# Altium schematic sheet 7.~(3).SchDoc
size 420 x 297 mm
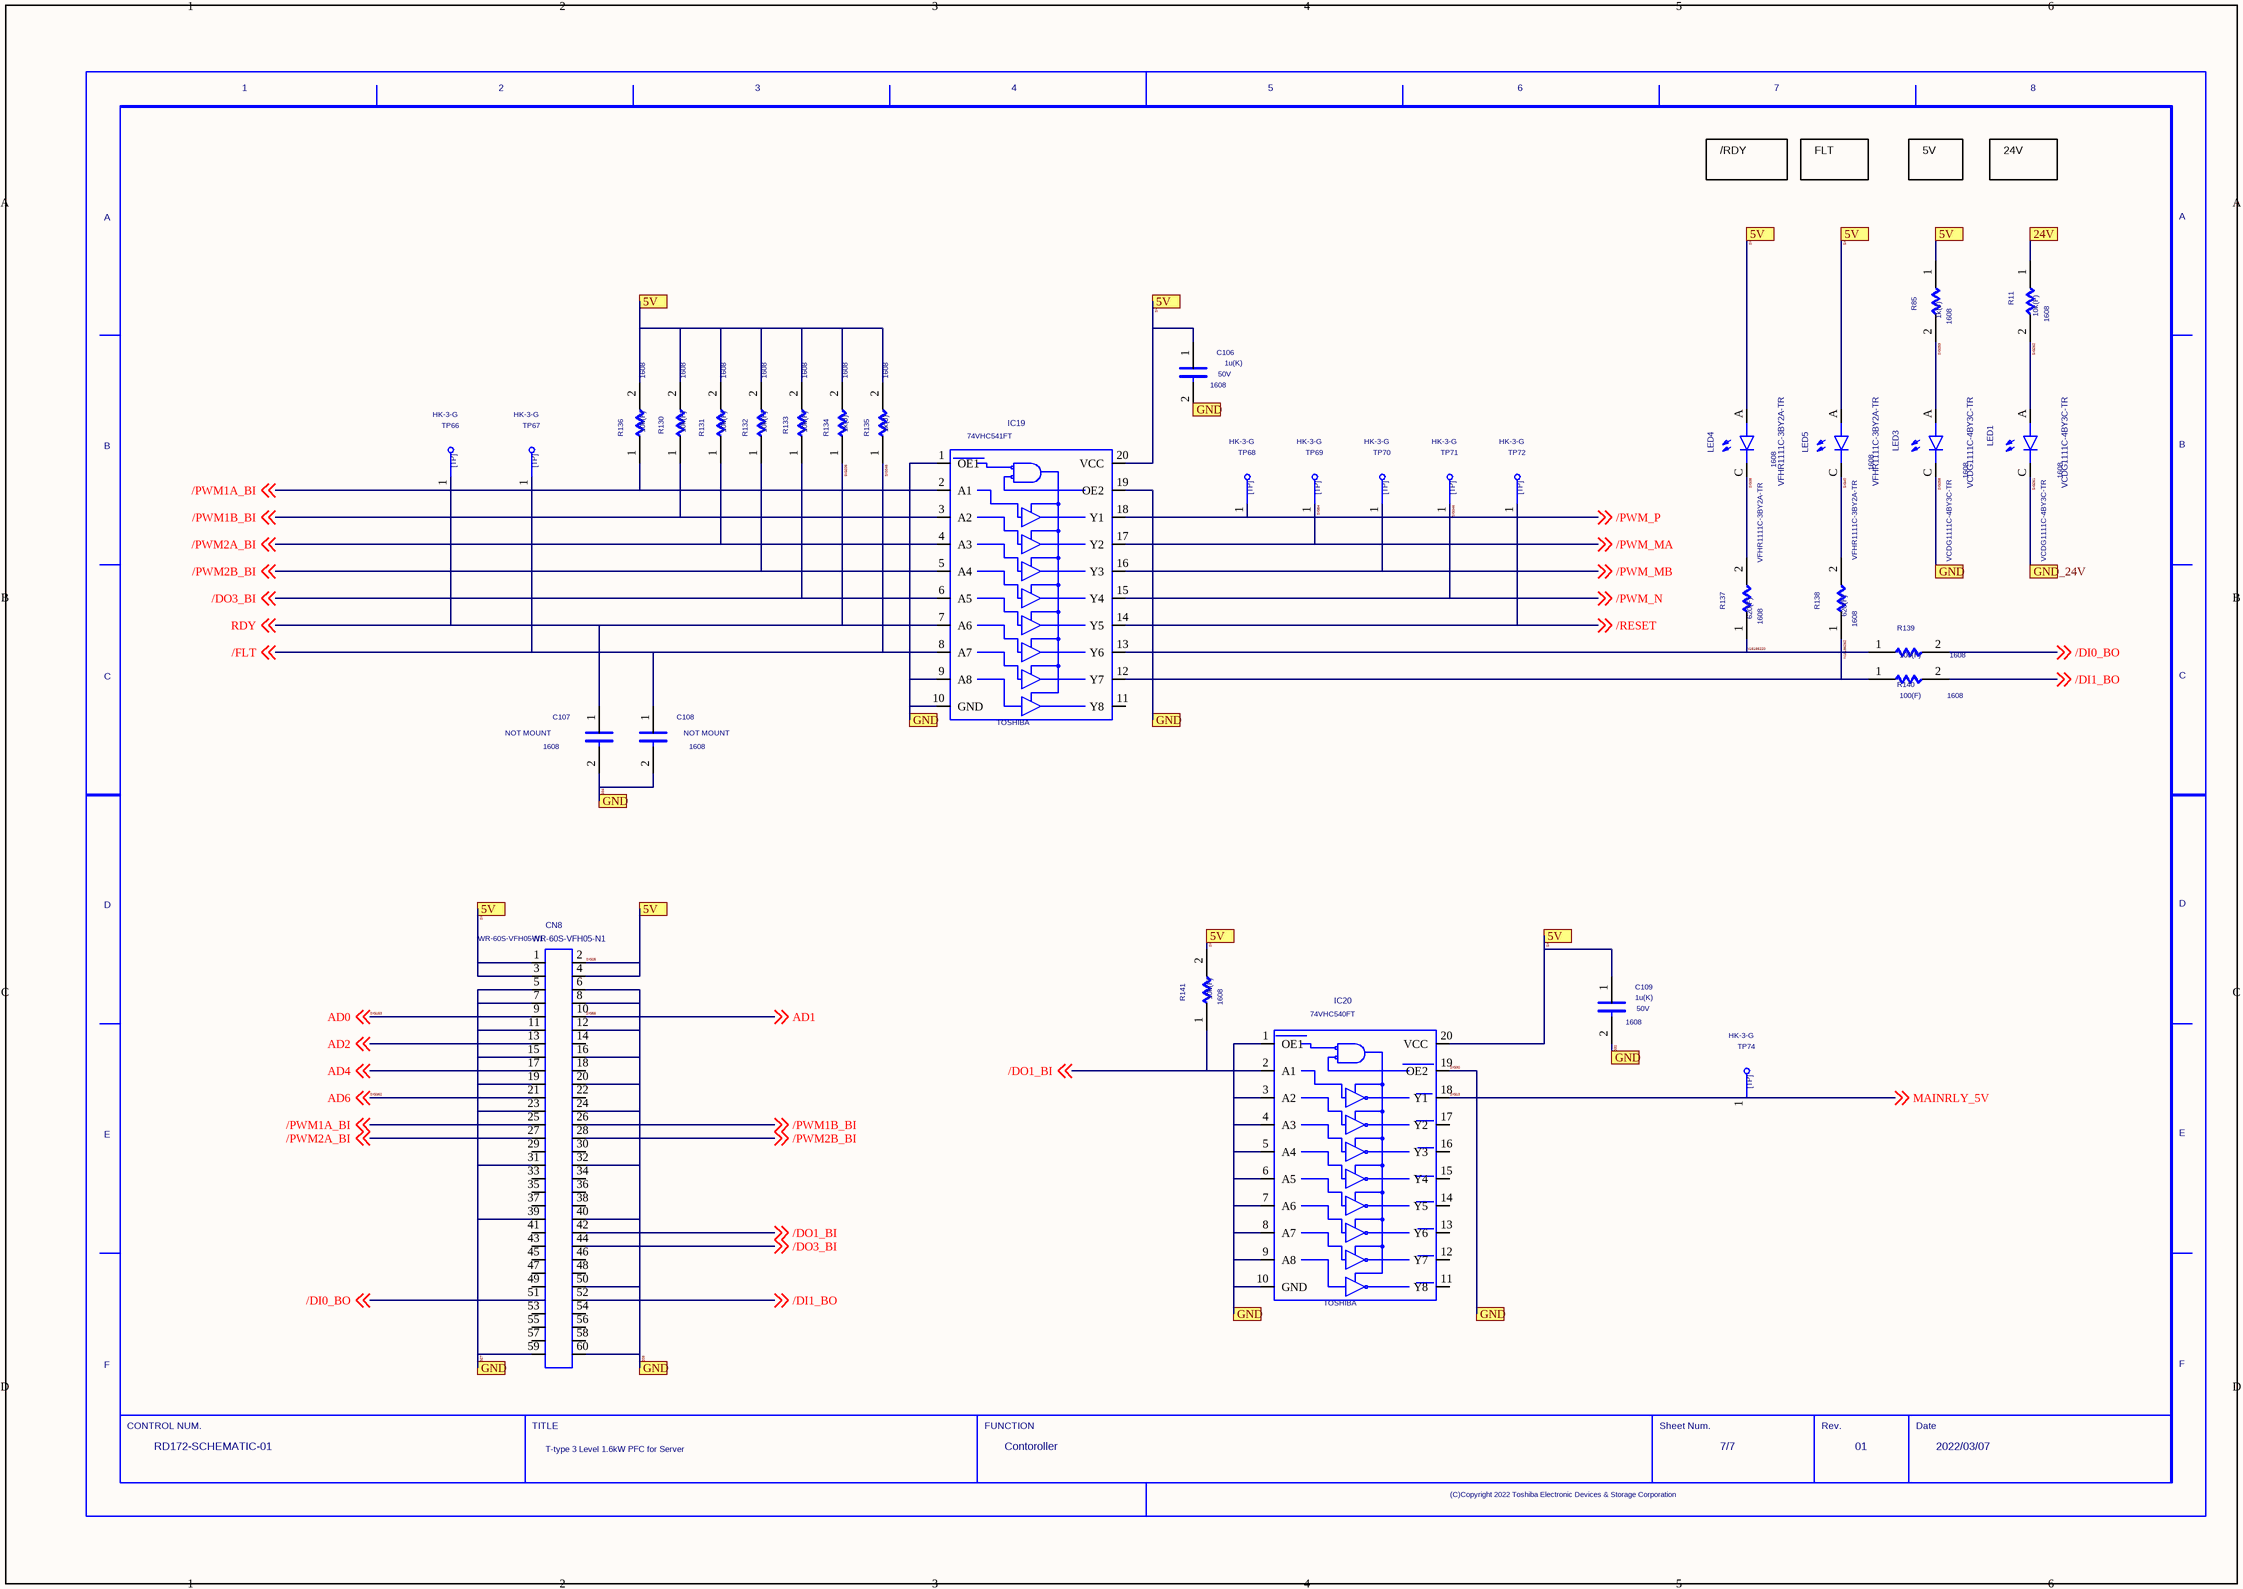
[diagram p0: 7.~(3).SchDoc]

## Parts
C106  SIZECODESMD: 1608  VAL2: 50V  VAL1: 1u(K)  (hidden comment: C)
C107  SIZECODESMD: 1608  NOTMOUNT: NOT MOUNT  (hidden comment: C)
C108  SIZECODESMD: 1608  NOTMOUNT: NOT MOUNT  (hidden comment: C)
C109  SIZECODESMD: 1608  VAL2: 50V  VAL1: 1u(K)  (hidden comment: C)
CN8  WR-60S-VFH05-N1
IC19  USERCOMPTEXT3: TOSHIBA  (hidden comment: 74VHC541FT)
IC20  USERCOMPTEXT3: TOSHIBA  (hidden comment: 74VHC540FT)
LED1  VCDG1111C-4BY3C-TR  SIZECODESMD: 1608
LED3  VCDG1111C-4BY3C-TR  SIZECODESMD: 1608
LED4  VFHR1111C-3BY2A-TR  SIZECODESMD: 1608
LED5  VFHR1111C-3BY2A-TR  SIZECODESMD: 1608
R11  SIZECODESMD: 1608  VAL1: 10k(F)  (hidden comment: R)
R85  SIZECODESMD: 1608  VAL1: 1k(J)  (hidden comment: R)
R130  SIZECODESMD: 1608  VAL1: 10k(F)  (hidden comment: R)
R131  SIZECODESMD: 1608  VAL1: 10k(F)  (hidden comment: R)
R132  SIZECODESMD: 1608  VAL1: 10k(F)  (hidden comment: R)
R133  SIZECODESMD: 1608  VAL1: 10k(F)  (hidden comment: R)
R134  SIZECODESMD: 1608  VAL1: 1k(J)  (hidden comment: R)
R135  SIZECODESMD: 1608  VAL1: 1k(J)  (hidden comment: R)
R136  SIZECODESMD: 1608  VAL1: 10k(F)  (hidden comment: R)
R137  SIZECODESMD: 1608  VAL1: 620(F)  (hidden comment: R)
R138  SIZECODESMD: 1608  VAL1: 620(F)  (hidden comment: R)
R139  SIZECODESMD: 1608  VAL1: 100(F)  (hidden comment: R)
R140  SIZECODESMD: 1608  VAL1: 100(F)  (hidden comment: R)
R141  SIZECODESMD: 1608  VAL1: 10k(F)  (hidden comment: R)
TP66  VAL3: HK-3-G  (hidden comment: TP)
TP67  VAL3: HK-3-G  (hidden comment: TP)
TP68  VAL3: HK-3-G  (hidden comment: TP)
TP69  VAL3: HK-3-G  (hidden comment: TP)
TP70  VAL3: HK-3-G  (hidden comment: TP)
TP71  VAL3: HK-3-G  (hidden comment: TP)
TP72  VAL3: HK-3-G  (hidden comment: TP)
TP74  VAL3: HK-3-G  (hidden comment: TP)
U?  DATE: 2022/03/07  REVISION: 01  SHEETNUMBER: 7/7  FUNCTION: Contoroller  TITLE: T-type 3 Level 1.6kW PFC for Server  DRAWINGNUMBER: RD172-SCHEMATIC-01  (hidden comment: WAKU_DEF100)

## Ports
5V, 24V, GND, GND_24V

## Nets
24V: R11.1 ; port 24V
/DI0_BO: CN8.51 R139.2 ; off-sheet /DI0_BO
/DI1_BO: CN8.52 R140.2 ; off-sheet /DI1_BO
/DO1_BI: CN8.42 IC20.2(A1) R141.1 ; off-sheet /DO1_BI
/DO3_BI: CN8.44 IC19.6(A5) R133.1 ; off-sheet /DO3_BI
/PWM1A_BI: CN8.25 IC19.2(A1) R136.1 ; off-sheet /PWM1A_BI
/PWM1B_BI: CN8.26 IC19.3(A2) R130.1 ; off-sheet /PWM1B_BI
/PWM2A_BI: CN8.27 IC19.4(A3) R131.1 ; off-sheet /PWM2A_BI
/PWM2B_BI: CN8.28 IC19.5(A4) R132.1 ; off-sheet /PWM2B_BI
/PWM_MB: IC19.16(Y3) TP70.1 ; off-sheet /PWM_MB
/PWM_P: IC19.18(Y1) TP68.1 ; off-sheet /PWM_P
/RESET: IC19.14(Y5) TP72.1 ; off-sheet /RESET
AD2: CN8.13 ; off-sheet AD2
AD4: CN8.17 ; off-sheet AD4
N18186220: IC19.13(Y6) R137.1 R139.1
N18186262: IC19.12(Y7) R138.1 R140.1
SIG13: IC20.18(Y1) TP74.1 ; off-sheet MAINRLY_5V  [also labelled MAINRLY_5V]
SIG24: C106.1 C109.1 CN8.1 CN8.2 CN8.3 CN8.4 IC19.20(VCC) IC20.20(VCC) LED4.A LED5.A R85.1 R130.2 R131.2 R132.2 R133.2 R134.2 R135.2 R136.2 R141.2 ; port 5V  [also labelled SIG25, SIG28, SIG31, SIG36, SIG37, SIG39]
SIG38: LED4.C R137.2
SIG40: LED5.C R138.2
SIG55: CN8.10 ; off-sheet AD1  [also labelled AD1]
SIG84: IC19.17(Y2) TP69.1 ; off-sheet /PWM_MA  [also labelled /PWM_MA]
SIG153: CN8.9 ; off-sheet AD0  [also labelled AD0]
SIG205: C107.1 IC19.7(A6) R134.1 TP66.1 ; off-sheet RDY  [also labelled RDY]
SIG208: C106.2 C107.2 C108.2 C109.2 CN8.5 CN8.6 CN8.7 CN8.8 CN8.11 CN8.12 CN8.15 CN8.16 CN8.19 CN8.20 CN8.23 CN8.24 CN8.31 CN8.32 CN8.39 CN8.40 CN8.50 CN8.59 CN8.60 IC19.1(OE1) IC19.9(A8) IC19.10(GND) IC19.19(OE2) IC20.1(OE1) IC20.3(A2) IC20.4(A3) IC20.5(A4) IC20.6(A5) IC20.7(A6) IC20.8(A7) IC20.9(A8) IC20.10(GND) IC20.19(OE2) LED3.C ; port GND  [also labelled SIG258, SIG27, SIG30, SIG32, SIG34]
SIG259: LED3.A R85.2
SIG261: LED1.C ; port GND_24V
SIG262: LED1.A R11.2
SIG345: C108.1 IC19.8(A7) R135.1 TP67.1 ; off-sheet /FLT  [also labelled /FLT]
SIG346: IC19.15(Y4) TP71.1 ; off-sheet /PWM_N  [also labelled /PWM_N]
SIG362: CN8.21 ; off-sheet AD6  [also labelled AD6]

Not connected (* = marked no-connect by the designer): CN8 14 18 22 29 30 33 34 35 36 37 38 41 43 45 46 47 48 49 53 54 55 56 57 58; IC19 11(Y8); IC20 11(Y8) 12(Y7) 13(Y6) 14(Y5) 15(Y4) 16(Y3) 17(Y2)

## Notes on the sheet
- /RDY
- FLT
- 5V
- 24V

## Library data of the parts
C106 C109 = C: OriginalSymbolOrigin: (2540,7620); COMP: -C-UMK107AB7105KA-T
C107 C108 = C: OriginalSymbolOrigin: (2540,7620); COMP: -C-NC_C1608
CN8 = WR_60S_VFH05_N1: Terminal, 200V, 0.3A; MANUFACTURER: JAE; COMP: -CN-WR-60S-VFH05-N1; NOTE: 60pin; TIME: 16:53:54; UPDATEUSER: t5459927; UPDATETIME: 14:46:38; SAVECOUNT: 2; SAVEAREA0: -56595,-80318,58967,4405; OriginalSymbolOrigin: (0,0)
IC19 = 74VHC541FT_0: Buffer; COMP: -IC-74VHC541FT; TIME: 16:53:58; UPDATEUSER: t5459927; UPDATETIME: 14:50:23; SAVECOUNT: 2; SAVEAREA0: -22847,-24597,51708,30063; OriginalSymbolOrigin: (0,0)
IC20 = 74VHC540FT: Buffer; COMP: -IC-74VHC540FT; TIME: 16:53:55; UPDATEUSER: t5459927; UPDATETIME: 14:48:47; SAVECOUNT: 2; SAVEAREA0: -22628,-27657,51926,27001; OriginalSymbolOrigin: (0,0)
LED1 LED3 = VCDG1111C_4BY3C_TR: LED; MANUFACTURER: STANLEY; COMP: -LED-VCDG1111C-4BY3C-TR_AC; NOTE: Green; TIME: 16:53:54; UPDATEUSER: t5459927; SAVECOUNT: 1; OriginalSymbolOrigin: (0,-2540); INSTANCENAME: INS18172566
LED4 LED5 = VFHR1111C_3BY2A_TR: LED; MANUFACTURER: STANLEY; COMP: -LED-VFHR1111C-3BY2A-TR_AC; NOTE: Red; TIME: 16:53:54; UPDATEUSER: t5459927; SAVECOUNT: 1; OriginalSymbolOrigin: (0,-2540); INSTANCENAME: INS18256251
R11 R130-R133 R136 R141 = R: OriginalSymbolOrigin: (5080,5080); VAL2: 100mW; COMP: -R-ERJ3EKF1002V
R85 R134 R135 = R: OriginalSymbolOrigin: (5080,5080); VAL2: 125mW; COMP: -R-RK73B1JTTD102J
R137 R138 = R: OriginalSymbolOrigin: (5080,5080); COMP: -R-ERJ3EKF6200V; VAL2: 100mW
R139 R140 = R: OriginalSymbolOrigin: (5080,5080); COMP: -R-ERJ3EKF1000V; VAL2: 100mW
TP66-TP72 TP74 = TP: TIME: 16:12:21; UPDATEUSER: fukuda-y; UPDATETIME: 16:18:11; SAVECOUNT: 2; SAVEAREA0: -242,-92,12810,7836; OriginalSymbolOrigin: (0,7620); COMP: -TP-HK-3-G
U? = WAKU_DEF100: PLOTTIME: HH:MM; SAVEAREA0: 22200,72372,612276,319236; TIME: 14:30:25; UPDATEUSER: t5459927; UPDATETIME: 09:34:25; SAVECOUNT: 7; OriginalSymbolOrigin: (10160,284480)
